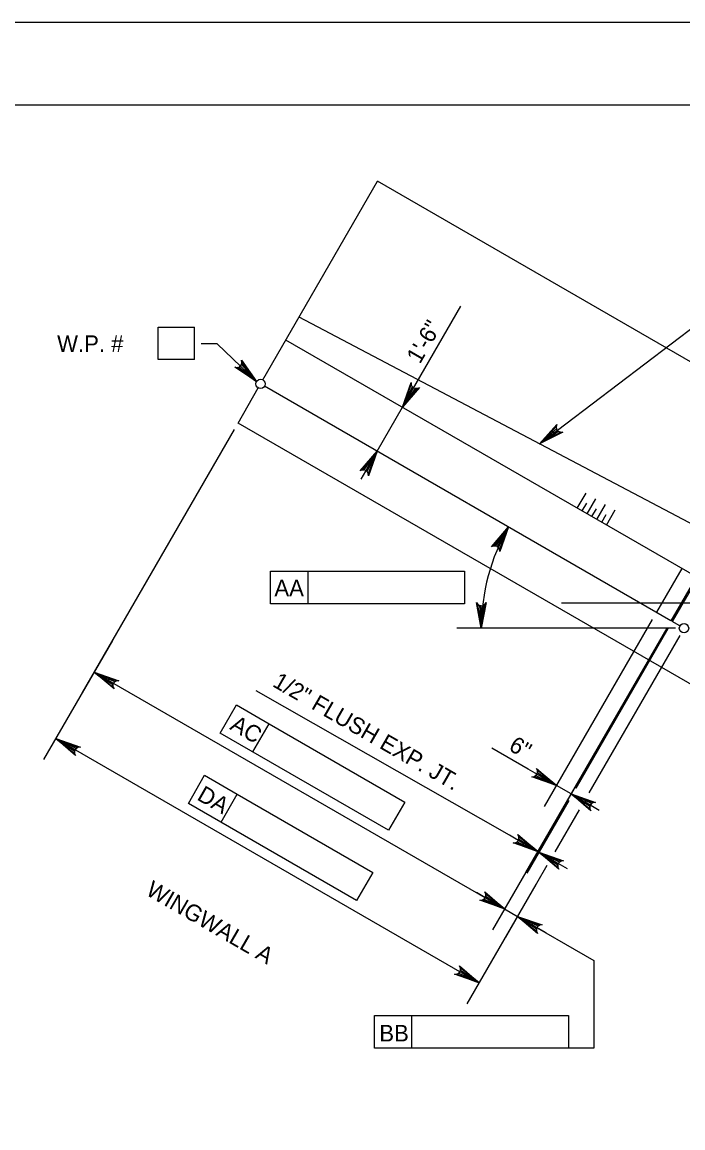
# Model space of a CAD drawing. Extents: x 638340 to 640242, y 295465 to 298435.
# Drawn here: x 638510 to 638629.9, y 298234.8 to 298435.5 of the extents above; entities that cross this region are included whole.
import ezdxf

# ---------------------------------------------------------------- set-up
doc = ezdxf.new("R2010")
doc.units = 0
for name, color, linetype in [('2', 7, 'Continuous'), ('Level 10', 7, 'Continuous'), ('Level 2', 7, 'Continuous'), ('Level 3', 7, 'Continuous'), ('PLT-BNDY', 7, 'Continuous')]:
    doc.layers.add(name, color=color, linetype=linetype)

msp = doc.modelspace()

# ---------------------------------------------------------------- linework, layer by layer
at = {"layer": '2'}
msp.add_line((638475.46, 298420.46), (639261.46, 298420.46), dxfattribs=at)
at = {"layer": 'Level 10'}
for p, q in [((638553.68, 298370.52), (638574.49, 298406.56)), ((638656.5, 298359.21), (638574.49, 298406.56)), ((638636.33, 298341.75), (638560.26, 298381.91)), ((638632.31, 298334.78), (638557.86, 298377.76)), ((638549.17, 298362.69), (638552.84, 298369.05)), ((638627.7, 298326.8), (638553.99, 298369.36)), ((638632.3, 298314.7), (638549.17, 298362.69)), ((638636.33, 298341.75), (638627.7, 298326.8)), ((638636.04, 298340.74), (638627.92, 298326.67)), ((638629.65, 298336.31), (638625.04, 298328.34)), ((638607.82, 298330.05), (638872.51, 298330.05)), ((638629.33, 298325.87), (638627.92, 298326.67))]:
    msp.add_line(p, q, dxfattribs=at)
at = {"layer": 'Level 2'}
for p, q in [((638610.71, 298347.25), (638612.29, 298349.98)), ((638611.6, 298346.74), (638612.41, 298348.14)), ((638612.48, 298346.22), (638614.06, 298348.95)), ((638614.25, 298345.2), (638615.83, 298347.93)), ((638613.37, 298345.71), (638614.18, 298347.11)), ((638615.14, 298344.69), (638615.95, 298346.09)), ((638616.03, 298344.18), (638617.6, 298346.91))]:
    msp.add_line(p, q, dxfattribs=at)
at = {"layer": 'Level 3'}
for p, q in [((638578.98, 298365.57), (638589.59, 298383.93)), ((638534.66, 298374.2), (638534.66, 298380.1)), ((638534.66, 298380.1), (638541.24, 298380.1)), ((638541.24, 298374.2), (638541.24, 298380.1)), ((638603.83, 298358.91), (638632.53, 298380.72)), ((638545.39, 298377.07), (638542.45, 298377.07)), ((638552.54, 298370.23), (638545.39, 298377.07)), ((638541.24, 298374.2), (638534.66, 298374.2)), ((638574.38, 298357.59), (638578.98, 298365.56)), ((638548.48, 298361.51), (638520.86, 298313.67)), ((638574.38, 298357.59), (638571.43, 298352.49)), ((638555.03, 298335.8), (638561.87, 298335.8)), ((638555.03, 298329.9), (638555.03, 298335.8)), ((638561.87, 298329.9), (638561.87, 298335.8)), ((638561.87, 298335.8), (638590.27, 298335.8)), ((638590.27, 298335.8), (638590.27, 298329.9)), ((638590.27, 298329.9), (638555.03, 298329.9)), ((638624.27, 298327.01), (638604.7, 298293.1)), ((638628.52, 298325.44), (638588.87, 298325.44)), ((638626.93, 298325.47), (638595.3, 298270.69)), ((638626.93, 298325.47), (638601.31, 298281.1)), ((638626.93, 298325.47), (638607.35, 298291.56)), ((638627.15, 298325.35), (638610.42, 298296.36)), ((638629.29, 298324.11), (638612.8, 298295.55)), ((638526.39, 298323.25), (638513.89, 298301.6)), ((638523.07, 298317.5), (638597.52, 298274.52)), ((638598.42, 298287.87), (638552.46, 298314.11)), ((638545.95, 298306.41), (638548.9, 298311.52)), ((638548.9, 298311.52), (638554.81, 298308.1)), ((638551.87, 298302.99), (638554.81, 298308.1)), ((638554.81, 298308.1), (638579.41, 298293.9)), ((638576.46, 298288.79), (638545.95, 298306.41)), ((638516.1, 298305.42), (638592.9, 298261.08)), ((638601.8, 298299.87), (638595.18, 298303.7)), ((638604.35, 298298.4), (638601.8, 298299.87)), ((638540.16, 298293.66), (638543.1, 298298.76)), ((638543.1, 298298.76), (638549.02, 298295.34)), ((638609.57, 298295.39), (638606.91, 298296.93)), ((638546.08, 298290.24), (638549.02, 298295.34)), ((638549.02, 298295.34), (638573.62, 298281.14)), ((638579.41, 298293.9), (638576.46, 298288.79)), ((638609.16, 298294.17), (638601.53, 298280.97)), ((638612.12, 298293.92), (638614.67, 298292.44)), ((638570.67, 298276.04), (638540.16, 298293.66)), ((638611.02, 298292.46), (638606.63, 298284.86)), ((638600.97, 298286.4), (638598.42, 298287.87)), ((638603.74, 298284.8), (638603.52, 298284.93)), ((638605.19, 298282.37), (638597.66, 298269.33)), ((638606.3, 298283.32), (638608.85, 298281.85)), ((638573.62, 298281.14), (638570.67, 298276.04)), ((638603.19, 298278.91), (638590.69, 298257.25)), ((638594.96, 298275.99), (638592.41, 298277.47)), ((638597.52, 298274.52), (638599.87, 298273.16)), ((638599.87, 298273.16), (638613.71, 298265.17)), ((638602.43, 298271.68), (638604.98, 298270.21)), ((638613.71, 298265.17), (638613.71, 298249.24)), ((638573.89, 298255.14), (638580.72, 298255.14)), ((638573.89, 298249.24), (638573.89, 298255.14)), ((638580.72, 298249.24), (638580.72, 298255.14)), ((638580.72, 298255.14), (638609.12, 298255.14)), ((638609.12, 298255.14), (638609.12, 298249.24)), ((638609.12, 298249.24), (638573.89, 298249.24)), ((638613.71, 298249.24), (638609.12, 298249.24))]:
    msp.add_line(p, q, dxfattribs=at)
for points in [[(638552.54, 298370.23), (638548.58, 298372.82), (638549.01, 298372.75), (638549.36, 298372.85), (638549.61, 298373.03), (638549.79, 298373.3), (638549.87, 298373.65), (638549.79, 298374.08), (638552.54, 298370.23), (638549.87, 298373.65), (638549.79, 298373.3), (638552.54, 298370.23), (638549.61, 298373.03), (638549.36, 298372.85), (638552.54, 298370.23), (638549.01, 298372.75)], [(638578.98, 298365.57), (638580.55, 298370.03), (638580.59, 298369.6), (638580.77, 298369.28), (638581.01, 298369.08), (638581.31, 298368.97), (638581.67, 298368.97), (638582.06, 298369.16), (638578.98, 298365.57), (638581.67, 298368.97), (638581.31, 298368.97), (638578.98, 298365.57), (638581.01, 298369.08), (638580.77, 298369.28), (638578.98, 298365.57), (638580.59, 298369.6)], [(638603.83, 298358.91), (638607.01, 298362.42), (638606.87, 298362.01), (638606.92, 298361.65), (638607.06, 298361.36), (638607.29, 298361.15), (638607.63, 298361.01), (638608.07, 298361.03), (638603.83, 298358.91), (638607.63, 298361.01), (638607.29, 298361.15), (638603.83, 298358.91), (638607.06, 298361.36), (638606.92, 298361.65), (638603.83, 298358.91), (638606.87, 298362.01)], [(638574.38, 298357.59), (638572.81, 298353.13), (638572.77, 298353.56), (638572.59, 298353.88), (638572.35, 298354.08), (638572.05, 298354.19), (638571.69, 298354.18), (638571.29, 298354), (638574.38, 298357.59), (638571.69, 298354.18), (638572.05, 298354.19), (638574.38, 298357.59), (638572.35, 298354.08), (638572.59, 298353.88), (638574.38, 298357.59), (638572.77, 298353.56)], [(638598.22, 298343.83), (638596.65, 298339.36), (638596.61, 298339.8), (638596.44, 298340.11), (638596.19, 298340.31), (638595.9, 298340.42), (638595.53, 298340.42), (638595.14, 298340.23), (638598.22, 298343.83), (638595.53, 298340.42), (638595.9, 298340.42), (638598.22, 298343.83), (638596.19, 298340.31), (638596.44, 298340.11), (638598.22, 298343.83), (638596.61, 298339.8)], [(638593.29, 298325.44), (638592.42, 298330.09), (638592.67, 298329.73), (638592.98, 298329.55), (638593.29, 298329.5), (638593.61, 298329.55), (638593.92, 298329.73), (638594.17, 298330.09), (638593.29, 298325.44), (638593.92, 298329.73), (638593.61, 298329.55), (638593.29, 298325.44), (638593.29, 298329.5), (638592.98, 298329.55), (638593.29, 298325.44), (638592.67, 298329.73)], [(638523.07, 298317.5), (638527.54, 298315.93), (638527.1, 298315.89), (638526.79, 298315.71), (638526.59, 298315.47), (638526.48, 298315.17), (638526.48, 298314.81), (638526.67, 298314.42), (638523.07, 298317.5), (638526.48, 298314.81), (638526.48, 298315.17), (638523.07, 298317.5), (638526.59, 298315.47), (638526.79, 298315.71), (638523.07, 298317.5), (638527.1, 298315.89)], [(638516.1, 298305.42), (638520.57, 298303.85), (638520.13, 298303.82), (638519.82, 298303.64), (638519.61, 298303.4), (638519.5, 298303.1), (638519.51, 298302.74), (638519.69, 298302.34), (638516.1, 298305.42), (638519.51, 298302.74), (638519.5, 298303.1), (638516.1, 298305.42), (638519.61, 298303.4), (638519.82, 298303.64), (638516.1, 298305.42), (638520.13, 298303.82)], [(638606.91, 298296.93), (638602.44, 298298.49), (638602.88, 298298.53), (638603.19, 298298.71), (638603.39, 298298.95), (638603.5, 298299.25), (638603.5, 298299.61), (638603.31, 298300.01), (638606.91, 298296.93), (638603.5, 298299.61), (638603.5, 298299.25), (638606.91, 298296.93), (638603.39, 298298.95), (638603.19, 298298.71), (638606.91, 298296.93), (638602.88, 298298.53)], [(638609.57, 298295.39), (638614.03, 298293.82), (638613.59, 298293.79), (638613.28, 298293.61), (638613.08, 298293.36), (638612.97, 298293.07), (638612.97, 298292.7), (638613.16, 298292.31), (638609.57, 298295.39), (638612.97, 298292.7), (638612.97, 298293.07), (638609.57, 298295.39), (638613.08, 298293.36), (638613.28, 298293.61), (638609.57, 298295.39), (638613.59, 298293.79)], [(638603.52, 298284.93), (638599.06, 298286.49), (638599.49, 298286.53), (638599.81, 298286.71), (638600.01, 298286.95), (638600.12, 298287.25), (638600.12, 298287.61), (638599.93, 298288.01), (638603.52, 298284.93), (638600.12, 298287.61), (638600.12, 298287.25), (638603.52, 298284.93), (638600.01, 298286.95), (638599.81, 298286.71), (638603.52, 298284.93), (638599.49, 298286.53)], [(638603.74, 298284.8), (638608.21, 298283.23), (638607.77, 298283.19), (638607.46, 298283.01), (638607.26, 298282.77), (638607.15, 298282.47), (638607.15, 298282.11), (638607.34, 298281.71), (638603.74, 298284.8), (638607.15, 298282.11), (638607.15, 298282.47), (638603.74, 298284.8), (638607.26, 298282.77), (638607.46, 298283.01), (638603.74, 298284.8), (638607.77, 298283.19)], [(638597.52, 298274.52), (638593.05, 298276.09), (638593.49, 298276.13), (638593.8, 298276.3), (638594, 298276.55), (638594.11, 298276.84), (638594.11, 298277.2), (638593.92, 298277.6), (638597.52, 298274.52), (638594.11, 298277.2), (638594.11, 298276.84), (638597.52, 298274.52), (638594, 298276.55), (638593.8, 298276.3), (638597.52, 298274.52), (638593.49, 298276.13)], [(638599.87, 298273.16), (638604.34, 298271.59), (638603.9, 298271.55), (638603.59, 298271.37), (638603.39, 298271.13), (638603.28, 298270.83), (638603.28, 298270.47), (638603.47, 298270.07), (638599.87, 298273.16), (638603.28, 298270.47), (638603.28, 298270.83), (638599.87, 298273.16), (638603.39, 298271.13), (638603.59, 298271.37), (638599.87, 298273.16), (638603.9, 298271.55)], [(638592.9, 298261.08), (638588.44, 298262.65), (638588.87, 298262.69), (638589.19, 298262.87), (638589.39, 298263.11), (638589.5, 298263.41), (638589.5, 298263.77), (638589.31, 298264.16), (638592.9, 298261.08), (638589.5, 298263.77), (638589.5, 298263.41), (638592.9, 298261.08), (638589.39, 298263.11), (638589.19, 298262.87), (638592.9, 298261.08), (638588.87, 298262.69)]]:
    msp.add_lwpolyline(points, dxfattribs=at)
for points in [[(638550.75, 298372.63), (638550.07, 298371.92), (638552.54, 298370.23)], [(638580.03, 298368.36), (638580.88, 298367.87), (638578.98, 298365.56)], [(638606.73, 298360.48), (638606.12, 298361.28), (638604.04, 298359.07)], [(638572.48, 298355.28), (638573.33, 298354.79), (638574.38, 298357.59)], [(638596.42, 298341.44), (638597.28, 298340.99), (638598.22, 298343.82)], [(638593.9, 298328.37), (638592.92, 298328.4), (638593.29, 298325.44)], [(638525.87, 298316.45), (638525.38, 298315.6), (638523.07, 298317.5)], [(638518.9, 298304.38), (638518.41, 298303.52), (638516.1, 298305.42)], [(638604.6, 298298.82), (638604.11, 298297.97), (638606.91, 298296.93)], [(638612.36, 298294.34), (638611.87, 298293.49), (638609.57, 298295.39)], [(638601.22, 298286.82), (638600.73, 298285.97), (638603.52, 298284.93)], [(638606.54, 298283.75), (638606.05, 298282.9), (638603.74, 298284.8)], [(638595.21, 298276.42), (638594.72, 298275.57), (638597.52, 298274.52)], [(638602.67, 298272.11), (638602.18, 298271.26), (638599.87, 298273.16)], [(638590.6, 298262.98), (638590.1, 298262.13), (638592.9, 298261.08)]]:
    msp.add_lwpolyline(points, close=True, dxfattribs=at)
for centre in [(638553.26, 298369.78), (638630.06, 298325.44)]:
    msp.add_circle(centre, 0.849, dxfattribs=at)
for start, end in [(149.9988, 180), (174.95, 175.4061)]:
    msp.add_arc((638630.06, 298325.44), 36.77, start, end, dxfattribs=at)
at = {"layer": 'PLT-BNDY'}
msp.add_lwpolyline([(638435.46, 298435.46), (639276.46, 298435.46), (639276.46, 297841.46), (638435.46, 297841.46)], close=True, dxfattribs=at)

# ---------------------------------------------------------------- texts
at = {"layer": 'Level 3'}
for s, height, rotation, p in [('1\'-6"', 3, 60, (638582.15, 298373.27)), ('1/2" FLUSH EXP. JT.', 3.0001, 330, (638555.24, 298315)), ('AC', 3, 330, (638547.51, 298307.2)), ('6"', 3, 330, (638598.08, 298303.42)), ('DA', 3, 330.0005, (638541.54, 298294.42)), ('WINGWALL A', 3, 330.0005, (638532.24, 298277.18))]:
    msp.add_text(s, height=height, rotation=rotation, dxfattribs=at).set_placement(p)
for s, p in [('W.P. # ', (638516.35, 298375.6)), ('AA', (638555.76, 298331.25)), ('BB', (638574.79, 298250.45))]:
    msp.add_text(s, height=3, dxfattribs=at).set_placement(p)

doc.saveas('drawing.dxf')
